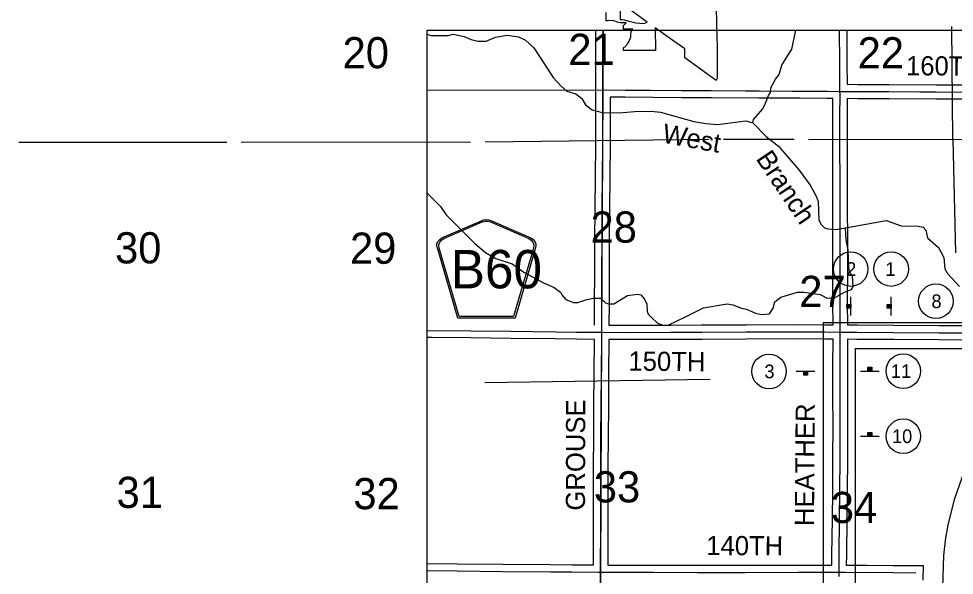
# Model space of a CAD drawing. Extents: x -2251611 to -2054719, y -2227156 to -2099355.
# Drawn here: x -2155960 to -2135345, y -2130114 to -2117859 of the extents above; entities that cross this region are included whole.
import ezdxf

# ---------------------------------------------------------------- set-up
doc = ezdxf.new("R2010")
doc.units = 0
for name, color, linetype in [('Default', 7, 'Continuous'), ('dsnTextFinalPlan', 7, 'Continuous'), ('dsnTextNote', 7, 'Continuous'), ('tdCoCorpBndry', 7, 'Continuous'), ('tdCoHydroRiver', 7, 'Continuous'), ('tdCoHydroTxtLg', 7, 'Continuous'), ('tdCoInt', 7, 'Continuous'), ('tdCoSecRdTxt', 7, 'Continuous'), ('tdCoSecRteBand', 7, 'Continuous'), ('tdCoSectLinePart', 7, 'Continuous'), ('tdCoSectNmbr', 7, 'Continuous'), ('tdCoShieldCoRte', 7, 'Continuous'), ('tdCoSurfAsphalt', 7, 'Continuous'), ('tdCoSurfGravel', 7, 'Continuous'), ('tdCoTwpBndry', 7, 'Continuous'), ('tdCoTwpBndryShd', 7, 'Continuous')]:
    doc.layers.add(name, color=color, linetype=linetype)

msp = doc.modelspace()

# ---------------------------------------------------------------- linework, layer by layer
at = {"layer": 'Default'}
for p, q in [((-2127105, -2124556), (-2138233, -2124556)), ((-2138233, -2124556), (-2138233, -2137572)), ((-2137524, -2138371), (-2137524, -2125114)), ((-2137524, -2125120), (-2127722, -2125120))]:
    msp.add_line(p, q, dxfattribs=at)
at = {"layer": 'dsnTextFinalPlan'}
for p, q in [((-2137705, -2124233), (-2137705, -2124149)), ((-2137701, -2124149), (-2137701, -2124233)), ((-2137697, -2124233), (-2137697, -2124149)), ((-2137693, -2124149), (-2137693, -2124233)), ((-2137689, -2124233), (-2137689, -2124149)), ((-2137683, -2124149), (-2137683, -2124233)), ((-2137680, -2124233), (-2137680, -2124149)), ((-2137673, -2124149), (-2137673, -2124233)), ((-2137667, -2124233), (-2137667, -2124149)), ((-2137663, -2124149), (-2137662, -2124233)), ((-2137659, -2124233), (-2137659, -2124149)), ((-2137655, -2124149), (-2137655, -2124233)), ((-2137650, -2124233), (-2137650, -2124149)), ((-2137647, -2124149), (-2137647, -2124233)), ((-2137644, -2124233), (-2137644, -2124149)), ((-2137640, -2124149), (-2137640, -2124233)), ((-2137636, -2124233), (-2137636, -2124149)), ((-2137632, -2124149), (-2137632, -2124233)), ((-2137626, -2124396), (-2137626, -2123983)), ((-2136816, -2124233), (-2136816, -2124149)), ((-2136811, -2124149), (-2136811, -2124233)), ((-2136808, -2124233), (-2136808, -2124149)), ((-2136803, -2124149), (-2136803, -2124233)), ((-2136800, -2124233), (-2136800, -2124149)), ((-2136793, -2124149), (-2136793, -2124233)), ((-2136790, -2124233), (-2136790, -2124149)), ((-2136784, -2124149), (-2136784, -2124233)), ((-2136778, -2124233), (-2136778, -2124149)), ((-2136773, -2124149), (-2136773, -2124233)), ((-2136770, -2124233), (-2136770, -2124149)), ((-2136766, -2124149), (-2136766, -2124233)), ((-2136761, -2124233), (-2136761, -2124149)), ((-2136758, -2124149), (-2136758, -2124233)), ((-2136754, -2124233), (-2136754, -2124149)), ((-2136750, -2124149), (-2136750, -2124233)), ((-2136747, -2124233), (-2136747, -2124149)), ((-2136742, -2124149), (-2136742, -2124233)), ((-2136736, -2124396), (-2136736, -2123983)), ((-2138415, -2125625), (-2138828, -2125625)), ((-2137412, -2125619), (-2136999, -2125619)), ((-2137249, -2125539), (-2137165, -2125539)), ((-2137165, -2125544), (-2137249, -2125544)), ((-2137249, -2125547), (-2137165, -2125547)), ((-2137165, -2125552), (-2137249, -2125552)), ((-2137249, -2125555), (-2137165, -2125555)), ((-2137165, -2125561), (-2137249, -2125562)), ((-2137249, -2125565), (-2137165, -2125565)), ((-2137165, -2125571), (-2137249, -2125571)), ((-2137249, -2125577), (-2137165, -2125577)), ((-2137165, -2125582), (-2137249, -2125582)), ((-2137249, -2125585), (-2137165, -2125585)), ((-2137165, -2125589), (-2137249, -2125589)), ((-2137249, -2125594), (-2137165, -2125594)), ((-2137165, -2125597), (-2137249, -2125597)), ((-2137249, -2125600), (-2137165, -2125600)), ((-2137165, -2125604), (-2137249, -2125604)), ((-2137249, -2125608), (-2137165, -2125608)), ((-2137165, -2125612), (-2137249, -2125612)), ((-2138662, -2125631), (-2138578, -2125631)), ((-2138578, -2125636), (-2138662, -2125636)), ((-2138662, -2125640), (-2138578, -2125640)), ((-2138578, -2125644), (-2138662, -2125644)), ((-2138662, -2125647), (-2138578, -2125647)), ((-2138578, -2125650), (-2138662, -2125650)), ((-2138662, -2125655), (-2138578, -2125655)), ((-2138578, -2125659), (-2138662, -2125659)), ((-2138662, -2125662), (-2138578, -2125662)), ((-2138578, -2125667), (-2138662, -2125667)), ((-2138662, -2125673), (-2138578, -2125673)), ((-2138578, -2125679), (-2138662, -2125679)), ((-2138662, -2125683), (-2138578, -2125682)), ((-2138578, -2125689), (-2138662, -2125689)), ((-2138662, -2125692), (-2138578, -2125692)), ((-2138578, -2125697), (-2138662, -2125697)), ((-2138662, -2125700), (-2138578, -2125700)), ((-2138578, -2125705), (-2138662, -2125705)), ((-2137412, -2127053), (-2136999, -2127053)), ((-2137249, -2126973), (-2137165, -2126973)), ((-2137165, -2126978), (-2137249, -2126978)), ((-2137249, -2126981), (-2137165, -2126981)), ((-2137165, -2126986), (-2137249, -2126986)), ((-2137249, -2126989), (-2137165, -2126989)), ((-2137165, -2126996), (-2137249, -2126996)), ((-2137249, -2126999), (-2137165, -2126999)), ((-2137165, -2127005), (-2137249, -2127005)), ((-2137249, -2127011), (-2137165, -2127011)), ((-2137165, -2127016), (-2137249, -2127016)), ((-2137249, -2127019), (-2137165, -2127019)), ((-2137165, -2127023), (-2137249, -2127023)), ((-2137249, -2127028), (-2137165, -2127028)), ((-2137165, -2127031), (-2137249, -2127031)), ((-2137249, -2127035), (-2137165, -2127035)), ((-2137165, -2127039), (-2137249, -2127039)), ((-2137249, -2127043), (-2137165, -2127043)), ((-2137165, -2127047), (-2137249, -2127047))]:
    msp.add_line(p, q, dxfattribs=at)
for points in [[(-2137627, -2124149), (-2137627, -2124233), (-2137711, -2124233), (-2137711, -2124149)], [(-2136738, -2124149), (-2136738, -2124233), (-2136822, -2124233), (-2136822, -2124149)], [(-2138662, -2125627), (-2138577, -2125627), (-2138577, -2125711), (-2138662, -2125711)], [(-2137165, -2125617), (-2137249, -2125617), (-2137249, -2125533), (-2137165, -2125533)], [(-2137165, -2127052), (-2137249, -2127052), (-2137249, -2126967), (-2137165, -2126967)]]:
    msp.add_lwpolyline(points, close=True, dxfattribs=at)
at = {"layer": 'dsnTextNote'}
msp.add_lwpolyline([(-2138305, -2118110), (-2124096, -2118110), (-2124096, -2144316), (-2146960, -2144316), (-2146960, -2118110), (-2138305, -2118110)], dxfattribs=at)
for centre in [(-2137628, -2123371), (-2136738, -2123371), (-2135750, -2124080), (-2139428, -2125625), (-2136469, -2125619), (-2136469, -2127053)]:
    msp.add_circle(centre, 381, dxfattribs=at)
at = {"layer": 'tdCoCorpBndry'}
for points in [[(-2142706, -2117679), (-2142708, -2117873), (-2142661, -2117878), (-2142618, -2117887), (-2142538, -2117904), (-2142450, -2117929), (-2142361, -2117947), (-2142271, -2117960), (-2142181, -2117964), (-2142110, -2117938), (-2143001, -2117283)], [(-2140593, -2117587), (-2140586, -2117986), (-2140586, -2118038), (-2140573, -2118469), (-2140568, -2118842), (-2140570, -2119171), (-2140582, -2119195), (-2140591, -2119220), (-2141283, -2118721), (-2141285, -2118521), (-2141601, -2118303), (-2141940, -2118058), (-2141932, -2118557), (-2142634, -2118561), (-2142634, -2118499), (-2142617, -2118487), (-2142601, -2118476), (-2142586, -2118460), (-2142573, -2118443), (-2142559, -2118426), (-2142545, -2118409), (-2142533, -2118391), (-2142517, -2118370), (-2142509, -2118354), (-2142499, -2118334), (-2142490, -2118311), (-2142485, -2118294), (-2142480, -2118280), (-2142473, -2118259), (-2142473, -2118233), (-2142469, -2118193), (-2142462, -2118155), (-2142452, -2118119), (-2142429, -2118090), (-2142633, -2118091), (-2142632, -2118005), (-2142572, -2117953), (-2142710, -2117953), (-2142765, -2117932), (-2142845, -2117904), (-2142861, -2117902), (-2142890, -2117903), (-2142935, -2117900), (-2142970, -2117903), (-2142995, -2117904), (-2143019, -2117905), (-2143019, -2117885), (-2143019, -2117719)]]:
    msp.add_lwpolyline(points, dxfattribs=at)
at = {"layer": 'tdCoHydroRiver'}
for points in [[(-2146960, -2118197), (-2146876, -2118227), (-2146501, -2118227), (-2146384, -2118202), (-2146142, -2118252), (-2145992, -2118318), (-2145842, -2118352), (-2145659, -2118351), (-2145451, -2118268)], [(-2139785, -2120152), (-2139768, -2120077), (-2139561, -2119843), (-2139502, -2119718), (-2139436, -2119551), (-2139395, -2119484), (-2139387, -2119384), (-2139287, -2119192), (-2139204, -2119084), (-2139146, -2118884), (-2139088, -2118783), (-2138922, -2118533), (-2138835, -2118110)], [(-2145451, -2118268), (-2145201, -2118218), (-2144951, -2118259), (-2144793, -2118334), (-2144609, -2118501), (-2144184, -2119150), (-2144009, -2119342), (-2143883, -2119458), (-2143683, -2119516), (-2143550, -2119616), (-2143474, -2119757), (-2143323, -2119865), (-2143106, -2119923), (-2142729, -2119930), (-2142394, -2119904), (-2142026, -2119894)], [(-2142026, -2119894), (-2141817, -2119918), (-2141081, -2120124), (-2140821, -2120164), (-2140562, -2120188), (-2139935, -2120111), (-2139785, -2120152)], [(-2139785, -2120152), (-2139492, -2120451), (-2139217, -2120667), (-2138766, -2121191), (-2138523, -2121523), (-2138390, -2121765), (-2138348, -2121881), (-2138330, -2122290), (-2138288, -2122381), (-2138205, -2122464), (-2138130, -2122489), (-2137955, -2122497), (-2137746, -2122463)], [(-2146960, -2121698), (-2146664, -2121993), (-2146539, -2122177), (-2145914, -2122801), (-2145672, -2123009), (-2145447, -2123142), (-2145089, -2123259), (-2144830, -2123442), (-2144397, -2123675), (-2144163, -2123774), (-2144021, -2123883), (-2143996, -2123941), (-2143905, -2124041), (-2143738, -2124107), (-2143638, -2124107), (-2143463, -2124049), (-2143305, -2124015), (-2143138, -2124015), (-2143030, -2124115), (-2142963, -2124140), (-2142846, -2124140), (-2142547, -2123956), (-2142322, -2123923), (-2142253, -2123940), (-2142175, -2124034), (-2142122, -2124144), (-2142110, -2124295), (-2142092, -2124363), (-2142023, -2124431)], [(-2137746, -2122463), (-2136847, -2122303), (-2136513, -2122419), (-2136138, -2122426), (-2136030, -2122451), (-2135971, -2122517), (-2135938, -2122684), (-2135696, -2122900), (-2135578, -2123116), (-2135553, -2123366), (-2135494, -2123466), (-2135227, -2123757)], [(-2142023, -2124431), (-2141888, -2124564), (-2141771, -2124606), (-2141636, -2124598), (-2141266, -2124425), (-2140872, -2124226), (-2140350, -2124136), (-2140225, -2124160), (-2140034, -2124235), (-2139925, -2124251), (-2139725, -2124342), (-2139592, -2124375), (-2139417, -2124358), (-2139334, -2124233), (-2139301, -2124092), (-2139168, -2123991), (-2138801, -2123882), (-2138660, -2123882), (-2138301, -2123931), (-2138143, -2124014), (-2137968, -2123997), (-2137768, -2123880), (-2137610, -2123821), (-2137577, -2123763), (-2137586, -2123521), (-2137644, -2123446), (-2137669, -2123346), (-2137687, -2122946), (-2137729, -2122730), (-2137746, -2122463)]]:
    msp.add_lwpolyline(points, dxfattribs=at)
at = {"layer": 'tdCoInt'}
msp.add_lwpolyline([(-2135593, -2137727), (-2135583, -2135365), (-2135600, -2134511), (-2135598, -2130378), (-2135576, -2129678), (-2135530, -2129293), (-2135473, -2128972), (-2135332, -2128427), (-2135169, -2127960), (-2134429, -2125998), (-2134077, -2125064)], dxfattribs=at)
at = {"layer": 'tdCoSecRteBand'}
for points in [[(-2143272, -2124605), (-2143270, -2124131), (-2143268, -2123441), (-2143268, -2123441), (-2143268, -2123441), (-2143266, -2122765), (-2143266, -2122765), (-2143266, -2122764), (-2143259, -2122038), (-2143259, -2122038), (-2143259, -2122038), (-2143253, -2121355), (-2143247, -2120621), (-2143247, -2119888), (-2143247, -2119888), (-2143247, -2119887), (-2143246, -2119584), (-2143247, -2119584), (-2143246, -2119426), (-2143245, -2119156), (-2143241, -2118110)], [(-2137714, -2118110), (-2137714, -2118198), (-2137714, -2118198), (-2137714, -2118199), (-2137711, -2118847), (-2137707, -2119300), (-2137707, -2119302), (-2137704, -2119302), (-2137467, -2119304), (-2136790, -2119307), (-2136790, -2119307), (-2136790, -2119307), (-2135747, -2119312), (-2134932, -2119315)], [(-2142603, -2124607), (-2141594, -2124606), (-2140912, -2124603), (-2139931, -2124596), (-2139930, -2124596), (-2139929, -2124596), (-2138864, -2124594), (-2138864, -2124594), (-2138864, -2124594), (-2138200, -2124597), (-2138199, -2124597), (-2138199, -2124597), (-2138017, -2124598), (-2138020, -2124129), (-2138020, -2124128), (-2138020, -2124127), (-2138019, -2123387), (-2138019, -2122685), (-2138020, -2122042), (-2138022, -2121389), (-2138024, -2120718), (-2138024, -2120718), (-2138024, -2120717), (-2138023, -2120035), (-2138023, -2120035), (-2138023, -2120035), (-2138022, -2119617), (-2138143, -2119616), (-2138757, -2119612), (-2139649, -2119608), (-2139649, -2119608), (-2139649, -2119608), (-2140704, -2119601), (-2141358, -2119600), (-2141359, -2119600), (-2141359, -2119600), (-2142598, -2119589), (-2142930, -2119587), (-2142931, -2119888), (-2142931, -2120621), (-2142931, -2120622), (-2142931, -2120622), (-2142936, -2121358), (-2142936, -2121358), (-2142936, -2121358), (-2142942, -2122041), (-2142949, -2122767), (-2142952, -2123442), (-2142953, -2124132), (-2142953, -2124132), (-2142953, -2124132), (-2142955, -2124606), (-2142603, -2124607)], [(-2134933, -2119631), (-2135748, -2119629), (-2135748, -2119629), (-2135748, -2119629), (-2136791, -2119624), (-2137468, -2119621), (-2137468, -2119621), (-2137469, -2119621), (-2137705, -2119619), (-2137706, -2120036), (-2137707, -2120717), (-2137705, -2121387), (-2137705, -2121388), (-2137705, -2121388), (-2137703, -2122041), (-2137702, -2122685), (-2137702, -2122685), (-2137702, -2122685), (-2137702, -2123387), (-2137702, -2123387), (-2137702, -2123387), (-2137703, -2124127), (-2137700, -2124601), (-2137489, -2124602), (-2137489, -2124602), (-2137489, -2124602), (-2136677, -2124609), (-2135680, -2124614), (-2135680, -2124614), (-2135680, -2124614), (-2135174, -2124617)], [(-2143297, -2129886), (-2143297, -2129868), (-2143293, -2129160), (-2143296, -2128460), (-2143296, -2128460), (-2143296, -2128459), (-2143294, -2127703), (-2143294, -2127702), (-2143294, -2127702), (-2143289, -2127081), (-2143285, -2126377), (-2143285, -2126377), (-2143285, -2126376), (-2143280, -2125679), (-2143280, -2125678), (-2143280, -2125678), (-2143274, -2124922), (-2143670, -2124918), (-2143670, -2124918), (-2143671, -2124918), (-2144137, -2124911), (-2145122, -2124901), (-2145123, -2124901), (-2145123, -2124901), (-2146000, -2124888), (-2146858, -2124881), (-2146960, -2124881)], [(-2141004, -2129893), (-2139964, -2129893), (-2138787, -2129890), (-2138787, -2129890), (-2138787, -2129890), (-2138042, -2129890), (-2138042, -2129888), (-2138041, -2129670), (-2138041, -2129669), (-2138041, -2129669), (-2138032, -2128871), (-2138025, -2128260), (-2138019, -2127535), (-2138016, -2126824), (-2138018, -2126161), (-2138018, -2126160), (-2138018, -2126160), (-2138018, -2125509), (-2138018, -2125509), (-2138018, -2125509), (-2138015, -2124915), (-2138017, -2124915), (-2138201, -2124914), (-2138864, -2124911), (-2139929, -2124912), (-2140910, -2124920), (-2140910, -2124920), (-2140910, -2124920), (-2141593, -2124923), (-2141593, -2124923), (-2141593, -2124923), (-2142603, -2124924), (-2142603, -2124924), (-2142604, -2124924), (-2142957, -2124923), (-2142957, -2124923), (-2142957, -2124924), (-2142957, -2124924), (-2142963, -2125681), (-2142968, -2126379), (-2142972, -2127083), (-2142972, -2127083), (-2142972, -2127083), (-2142978, -2127704), (-2142979, -2128459), (-2142976, -2129160), (-2142976, -2129160), (-2142976, -2129161), (-2142980, -2129869), (-2142980, -2129869), (-2142980, -2129869), (-2142980, -2129888), (-2142882, -2129888), (-2142615, -2129888), (-2142615, -2129888), (-2142615, -2129888), (-2141983, -2129889), (-2141983, -2129889), (-2141983, -2129889), (-2141004, -2129893)], [(-2135175, -2124934), (-2135681, -2124931), (-2136679, -2124925), (-2136679, -2124925), (-2136679, -2124925), (-2137492, -2124919), (-2137699, -2124917), (-2137701, -2125509), (-2137701, -2126160), (-2137700, -2126824), (-2137700, -2126824), (-2137700, -2126825), (-2137702, -2127537), (-2137702, -2127537), (-2137702, -2127538), (-2137709, -2128263), (-2137709, -2128263), (-2137709, -2128263), (-2137715, -2128874), (-2137715, -2128874), (-2137715, -2128874), (-2137724, -2129672), (-2137726, -2129888), (-2137512, -2129893), (-2137279, -2129890), (-2137278, -2129890), (-2137276, -2129890), (-2136693, -2129896), (-2136192, -2129899), (-2136033, -2129901), (-2136036, -2130218)], [(-2146960, -2129853), (-2146297, -2129859), (-2146297, -2129859), (-2146297, -2129859), (-2145293, -2129870), (-2144233, -2129877), (-2144233, -2129877), (-2144233, -2129877), (-2143766, -2129882), (-2143297, -2129886)]]:
    msp.add_lwpolyline(points, dxfattribs=at)
at = {"layer": 'tdCoSectLinePart'}
for points in [[(-2135375, -2120518), (-2135403, -2118031)], [(-2135375, -2120518), (-2130231, -2120452)], [(-2155960, -2120574), (-2151372, -2120577)], [(-2151056, -2120577), (-2146002, -2120573)], [(-2145685, -2120571), (-2140751, -2120514)], [(-2140434, -2120512), (-2138876, -2120514)], [(-2138556, -2120514), (-2135375, -2120518)], [(-2135375, -2120518), (-2135316, -2123011)], [(-2145692, -2125871), (-2140722, -2125799)]]:
    msp.add_lwpolyline(points, dxfattribs=at)
at = {"layer": 'tdCoShieldCoRte'}
for points in [[(-2146288, -2124452), (-2146721, -2122958), (-2146741, -2122889), (-2146745, -2122858), (-2146745, -2122816), (-2146723, -2122762), (-2146684, -2122717), (-2146634, -2122682), (-2145751, -2122300), (-2145711, -2122291), (-2145656, -2122286), (-2145601, -2122291), (-2145561, -2122300), (-2144678, -2122682), (-2144627, -2122717), (-2144589, -2122762), (-2144567, -2122816), (-2144567, -2122858), (-2144571, -2122889), (-2144591, -2122958), (-2145024, -2124452)], [(-2146257, -2124418), (-2146678, -2122965), (-2146698, -2122898), (-2146702, -2122868), (-2146702, -2122829), (-2146680, -2122776), (-2146643, -2122733), (-2146595, -2122700), (-2145747, -2122333), (-2145709, -2122325), (-2145656, -2122320), (-2145603, -2122325), (-2145565, -2122333), (-2144717, -2122700), (-2144669, -2122733), (-2144632, -2122776), (-2144610, -2122829), (-2144610, -2122868), (-2144614, -2122898), (-2144634, -2122965), (-2145055, -2124418)]]:
    msp.add_lwpolyline(points, close=True, dxfattribs=at)
at = {"layer": 'tdCoSurfAsphalt'}
for points in [[(-2143142, -2130531), (-2143140, -2130046), (-2143139, -2129868), (-2143135, -2129160), (-2143137, -2128460), (-2143136, -2127703), (-2143131, -2127082), (-2143127, -2126378), (-2143122, -2125680), (-2143115, -2124863), (-2143115, -2124764), (-2143111, -2124132), (-2143110, -2123441), (-2143107, -2122766), (-2143101, -2122039), (-2143094, -2121357), (-2143089, -2120621), (-2143089, -2119888), (-2143087, -2119427), (-2143086, -2119156), (-2143083, -2118110)], [(-2143115, -2124764), (-2142603, -2124766), (-2141593, -2124764), (-2140911, -2124762), (-2139929, -2124754), (-2138864, -2124753), (-2138200, -2124755), (-2137857, -2124758), (-2137490, -2124761), (-2136678, -2124767), (-2135681, -2124772), (-2135174, -2124775)]]:
    msp.add_lwpolyline(points, dxfattribs=at)
at = {"layer": 'tdCoSurfGravel'}
for points in [[(-2137864, -2119460), (-2137870, -2118848), (-2137873, -2118110)], [(-2143087, -2119427), (-2142597, -2119431), (-2141358, -2119442), (-2140703, -2119443), (-2139648, -2119450), (-2138756, -2119453), (-2138142, -2119457), (-2137864, -2119460), (-2137467, -2119463), (-2136790, -2119465), (-2135747, -2119470), (-2134932, -2119473), (-2134296, -2119476), (-2133382, -2119483)], [(-2137885, -2130141), (-2137885, -2130047), (-2137883, -2129671), (-2137874, -2128872), (-2137867, -2128262), (-2137861, -2127536), (-2137858, -2126824), (-2137859, -2126160), (-2137859, -2125509), (-2137857, -2124829), (-2137857, -2124758), (-2137862, -2124128), (-2137861, -2123387), (-2137861, -2122685), (-2137862, -2122042), (-2137863, -2121388), (-2137866, -2120717), (-2137864, -2120035), (-2137863, -2119513), (-2137864, -2119460), (-2137864, -2119460)], [(-2146960, -2124722), (-2145998, -2124729), (-2145121, -2124742), (-2144135, -2124753), (-2143668, -2124759), (-2143192, -2124764), (-2143115, -2124764)], [(-2146960, -2130012), (-2146298, -2130018), (-2145294, -2130028), (-2144235, -2130036), (-2143767, -2130040), (-2143198, -2130046), (-2143140, -2130046)], [(-2143140, -2130046), (-2142882, -2130047), (-2142615, -2130047), (-2141983, -2130047), (-2141004, -2130051), (-2139964, -2130051), (-2138787, -2130049), (-2138031, -2130049), (-2137885, -2130047), (-2137750, -2130046), (-2137513, -2130051), (-2137278, -2130049), (-2136694, -2130054), (-2136193, -2130058)]]:
    msp.add_lwpolyline(points, dxfattribs=at)
at = {"layer": 'tdCoTwpBndry'}
msp.add_lwpolyline([(-2146960, -2119432), (-2143248, -2119427)], dxfattribs=at)
at = {"layer": 'tdCoTwpBndryShd'}
for points in [[(-2143082, -2118110), (-2143089, -2119427), (-2143116, -2124764), (-2143141, -2130046), (-2143152, -2135314), (-2143161, -2140573), (-2143174, -2144316)], [(-2146960, -2119432), (-2143089, -2119427), (-2137866, -2119459), (-2132584, -2119484), (-2127311, -2119489), (-2124096, -2119501)]]:
    msp.add_lwpolyline(points, dxfattribs=at)

# ---------------------------------------------------------------- texts
at = {"layer": 'dsnTextNote'}
for s, p in [('2', (-2137728, -2123521)), ('1', (-2136863, -2123521)), ('8', (-2135849, -2124230)), ('3', (-2139529, -2125775)), ('11', (-2136743, -2125769)), ('10', (-2136718, -2127203))]:
    msp.add_text(s, height=300, dxfattribs=at).set_placement(p)
at = {"layer": 'tdCoHydroTxtLg'}
for s, rotation, p in [('West', 349.5976, (-2141800, -2120582)), ('Branch', 303.9496, (-2139730, -2120941))]:
    msp.add_text(s, height=422.4, rotation=rotation, dxfattribs=at).set_placement(p)
at = {"layer": 'tdCoSecRdTxt'}
for s, rotation, p in [('160TH', 359.6336, (-2136410, -2119104)), ('150TH', 359.4347, (-2142527, -2125607)), ('GROUSE', 89.8648, (-2143482, -2128690)), ('HEATHER', 89.5918, (-2138437, -2129031)), ('140TH', 359.7246, (-2140811, -2129669))]:
    msp.add_text(s, height=422.4, rotation=rotation, dxfattribs=at).set_placement(p)
at = {"layer": 'tdCoSectNmbr'}
for s, rotation, p in [('21', 0.0187, (-2143849, -2118876)), ('20', 0.0181, (-2148823, -2118951)), ('22', 0.0203, (-2137474, -2118953)), ('28', 0.0187, (-2143359, -2122790)), ('30', 0.0172, (-2153838, -2123247)), ('29', 0.0179, (-2148660, -2123255)), ('27', 0.0193, (-2138761, -2124207)), ('33', 0.0186, (-2143287, -2128510)), ('31', 0.0171, (-2153804, -2128632)), ('32', 0.0179, (-2148586, -2128659)), ('34', 0.0194, (-2138064, -2128964))]:
    msp.add_text(s, height=686.4, rotation=rotation, dxfattribs=at).set_placement(p)
at = {"layer": 'tdCoShieldCoRte'}
msp.add_text('B60', height=844.8, dxfattribs=at).set_placement((-2146440, -2123796))

doc.saveas('drawing.dxf')
